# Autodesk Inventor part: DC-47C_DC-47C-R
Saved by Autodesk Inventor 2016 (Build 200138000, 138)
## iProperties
Created: 2015-09
Part Number: DC-47C_DC-47C-R
Material: Generic
Document SubType Name: Modeling
Designer: irish_000
Density: 1 g/cm^3
Appearance: Default
Author: irish_000
Revision Number: ANY
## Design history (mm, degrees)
feature "Cut-Extrude3"
body "Solid1"
